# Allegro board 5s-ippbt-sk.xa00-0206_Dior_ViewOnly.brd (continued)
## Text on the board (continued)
GND: list("[Spacing] GND" "35.Shape to Route Keepout" "0 MIL [DEFAULT]" "0 MIL" "0.00 MIL" "DRC ERROR CLASS/GND" "[Shape] Route Keepout/All ((115.69 2506.43) (186.31 2577.05))" "[Gnd Shape] GND ((-373.71 -332.37) (4468.18 4481.96))" list(186.310000 2541.740000) nil)@@@list("amy_chou" "2015/01/12 09:57:41" nil "P143000034-PC" "5s-ippbt-sk.x01")@@@list("jennifer_hsu" "2015/01/12 14:36:47" nil "p143000039-pc" "5s-ippbt-sk.x01") | list("[Spacing] GND" "26.Shape to Route Keepout" "0 MIL [DEFAULT]" "0 MIL" "0.00 MIL" "DRC ERROR CLASS/GND" "[Shape] Route Keepout/All ((353.45 4291.46) (424.07 4362.08))" "[Gnd Shape] AGND ((-255.0 3453.0) (720.0 4400.0))" list(424.070000 4326.770000) nil)@@@list("amy_chou" "2015/01/12 09:57:36" nil "P143000034-PC" "5s-ippbt-sk.x01")@@@list("jennifer_hsu" "2015/01/12 14:36:44" nil "p143000039-pc" "5s-ippbt-sk.x01") | list("[Spacing] GND" "27.Shape to Route Keepout" "0 MIL [DEFAULT]" "0 MIL" "0.00 MIL" "DRC ERROR CLASS/GND" "[Shape] Route Keepout/All ((609.35 4291.46) (679.98 4362.08))" "[Gnd Shape] AGND ((-255.0 3453.0) (720.0 4400.0))" list(679.980000 4326.770000) nil)@@@list("amy_chou" "2015/01/12 09:57:37" nil "P143000034-PC" "5s-ippbt-sk.x01")@@@list("jennifer_hsu" "2015/01/12 14:36:45" nil "p143000039-pc" "5s-ippbt-sk.x01") | list("[Spacing] GND" "32.Shape to Route Keepout" "0 MIL [DEFAULT]" "0 MIL" "0.00 MIL" "DRC ERROR CLASS/GND" "[Shape] Route Keepout/All ((976.14 737.49) (1042.76 804.11))" "[Gnd Shape] GND ((-373.71 -332.37) (4468.18 4481.96))" list(1042.760000 770.800000) nil)@@@list("amy_chou" "2015/01/12 09:57:39" nil "P143000034-PC" "5s-ippbt-sk.x01")@@@list("jennifer_hsu" "2015/01/12 14:36:46" nil "p143000039-pc" "5s-ippbt-sk.x01") | list("[Spacing] GND" "28.Shape to Route Keepout" "0 MIL [DEFAULT]" "0 MIL" "0.00 MIL" "DRC ERROR CLASS/GND" "[Shape] Route Keepout/All ((1437.45 -325.97) (1524.07 -239.35))" "[Gnd Shape] GND ((-373.71 -332.37) (4468.18 4481.96))" list(1437.450000 -282.660000) nil)@@@list("amy_chou" "2015/01/12 09:57:37" nil "P143000034-PC" "5s-ippbt-sk.x01")@@@list("jennifer_hsu" "2015/01/12 14:36:45" nil "p143000039-pc" "5s-ippbt-sk.x01") | list("[Spacing] GND" "36.Shape to Route Keepout" "0 MIL [DEFAULT]" "0 MIL" "0.00 MIL" "DRC ERROR CLASS/GND" "[Shape] Route Keepout/All ((2391.48 4180.65) (2484.12 4273.28))" "[Gnd Shape] GND ((-373.71 -332.37) (4468.18 4481.96))" list(2484.120000 4226.970000) nil)@@@list("amy_chou" "2015/01/12 09:57:42" nil "P143000034-PC" "5s-ippbt-sk.x01")@@@list("jennifer_hsu" "2015/01/12 14:36:48" nil "p143000039-pc" "5s-ippbt-sk.x01") | list("[Spacing] GND" "37.Shape to Route Keepout" "0 MIL [DEFAULT]" "0 MIL" "0.00 MIL" "DRC ERROR CLASS/GND" "[Shape] Route Keepout/All ((2955.52 4114.02) (3036.14 4194.64))" "[Gnd Shape] GND ((-373.71 -332.37) (4468.18 4481.96))" list(3036.140000 4154.330000) nil)@@@list("amy_chou" "2015/01/12 09:57:42" nil "P143000034-PC" "5s-ippbt-sk.x01")@@@list("jennifer_hsu" "2015/01/12 14:36:48" nil "p143000039-pc" "5s-ippbt-sk.x01") | list("[Spacing] GND" "30.Shape to Route Keepout" "0 MIL [DEFAULT]" "0 MIL" "0.00 MIL" "DRC ERROR CLASS/GND" "[Shape] Route Keepout/All ((3031.18 -37.68) (3094.81 25.94))" "[Gnd Shape] GND ((-373.71 -332.37) (4468.18 4481.96))" list(3094.810000 -5.870000) nil)@@@list("amy_chou" "2015/01/12 09:57:38" nil "P143000034-PC" "5s-ippbt-sk.x01")@@@list("jennifer_hsu" "2015/01/12 14:36:46" nil "p143000039-pc" "5s-ippbt-sk.x01") | list("[Spacing] GND" "2.Shape to Route Keepout" "0 MIL [DEFAULT]" "0 MIL" "0.00 MIL" "DRC ERROR CLASS/GND" "[Shape] Route Keepout/All ((3082.5 3563.84) (3161.12 3642.46))" "[Gnd Shape] GND ((-373.71 -332.37) (4468.18 4481.96))" list(3121.810000 3642.460000) nil)@@@list("amy_chou" "2015/01/12 17:57:27" nil "P143000034-PC" "5s-ippbt-sk.x01")@@@list("jennifer_hsu" "2015/01/12 18:35:52" nil "p143000039-pc" "5s-ippbt-sk.x01") | list("[Spacing] GND" "29.Shape to Route Keepout" "0 MIL [DEFAULT]" "0 MIL" "0.00 MIL" "DRC ERROR CLASS/GND" "[Shape] Route Keepout/All ((3540.94 -76.81) (3604.57 -13.19))" "[Gnd Shape] GND ((-373.71 -332.37) (4468.18 4481.96))" list(3604.570000 -45.000000) nil)@@@list("amy_chou" "2015/01/12 09:57:38" nil "P143000034-PC" "5s-ippbt-sk.x01")@@@list("jennifer_hsu" "2015/01/12 14:36:45" nil "p143000039-pc" "5s-ippbt-sk.x01") | list("[Spacing] GND" "31.Shape to Route Keepout" "0 MIL [DEFAULT]" "0 MIL" "0.00 MIL" "DRC ERROR CLASS/GND" "[Shape] Route Keepout/All ((4155.45 329.33) (4242.07 415.95))" "[Gnd Shape] GND ((-373.71 -332.37) (4468.18 4481.96))" list(4242.070000 372.640000) nil)@@@list("amy_chou" "2015/01/12 09:57:39" nil "P143000034-PC" "5s-ippbt-sk.x01")@@@list("jennifer_hsu" "2015/01/12 14:36:46" nil "p143000039-pc" "5s-ippbt-sk.x01") | list("[Spacing] GND" "38.Shape to Route Keepin" "0 MIL [DEFAULT]" "0 MIL" "0.00 MIL" "DRC ERROR CLASS/GND" "[Shape] Route Keepin/All ((-373.71 -332.37) (4468.18 4481.96))" "[Gnd Shape] GND ((-373.71 -332.37) (4468.18 4481.96))" list(4299.650000 2680.720000) nil)@@@list("amy_chou" "2015/01/12 09:57:43" nil "P143000034-PC" "5s-ippbt-sk.x01")@@@list("jennifer_hsu" "2015/01/12 14:36:48" nil "p143000039-pc" "5s-ippbt-sk.x01") | list("[Spacing] GND" "33.Shape to Route Keepout" "0 MIL [DEFAULT]" "0 MIL" "0.00 MIL" "DRC ERROR CLASS/GND" "[Shape] Route Keepout/All ((4283.59 1394.18) (4509.57 1954.0))" "[Gnd Shape] GND ((-373.71 -332.37) (4468.18 4481.96))" list(4339.850000 1855.520000) nil)@@@list("amy_chou" "2015/01/12 09:57:40" nil "P143000034-PC" "5s-ippbt-sk.x01")@@@list("jennifer_hsu" "2015/01/12 14:36:47" nil "p143000039-pc" "5s-ippbt-sk.x01") | list("[Spacing] GND" "34.Shape to Route Keepout" "0 MIL [DEFAULT]" "0 MIL" "0.00 MIL" "DRC ERROR CLASS/GND" "[Shape] Route Keepout/All ((4243.45 2217.33) (4476.12 2781.09))" "[Gnd Shape] GND ((-373.71 -332.37) (4468.18 4481.96))" list(4468.180000 2780.380000) nil)@@@list("amy_chou" "2015/01/12 09:57:40" nil "P143000034-PC" "5s-ippbt-sk.x01")@@@list("jennifer_hsu" "2015/01/12 14:36:47" nil "p143000039-pc" "5s-ippbt-sk.x01")
User.28: R | 1 | 12 | 24 | 36 | E317539 | F2 | H14 | AU1 | CR6 | Y12 | SW10 | P13 | XBT1 | 2-4 | Clear CMOS | 1-3 | Clear PW | 3-4 | Default | P110 | E69 | P12 | TEL:(02)81439001 FAX:(02)28973868 | TAIPEI | www.pegatroncorp.com | DESIGNED BY PEGATRON CORPORATION | H1 | H3 | PCB MADE IN CHINA | REV:X01 | H4 | H2 | DESIGNER: | DATE: | LAY#: | 2015.01.12/18:38:52 | 5S-IPPBT-SK.X01 | AMY_CHOU | J56 | J27 | J8 | SFIS | J17 | J137 | J125 | E4 | ALL RIGHTS RESERVED | www.dell.com | COPYRIGHT 2015,01 | PJ1 | J218 | J11 | J133 | J219 | R&D DEPARTMENT/ENGINEER: | PROJECT DESCRIPTION: | MODEL NAME: | IPPBT-SK | BU5/Robert_Teng | Main Board | REV. | X01 | SILKSCREEN | PRIMARY-SIDE | N14939 | D33D66
User.29: 1 | 7 | 6 | 11 | 16 | 19 | 204 | 203 | 8 | 24 | 64 | 32 | 96 | 2 | 13 | H7 | H23 | H22 | XU1 | J134 | 14 | H20 | H21 | H8 | P70 | PU8 | PU3 | Y10 | LU1 | UU3 | Y24 | Y5 | U24 | PU9 | 21 | U23 | TEL:(02)81439001 FAX:(02)28973868 | TAIPEI | www.pegatroncorp.com | DESIGNED BY PEGATRON CORPORATION | DESIGNER: | DATE: | LAY#: | 2015.01.12/18:38:52 | 5S-IPPBT-SK.X01 | AMY_CHOU | XMM1 | R&D DEPARTMENT/ENGINEER: | PROJECT DESCRIPTION: | MODEL NAME: | IPPBT-SK | BU5/Robert_Teng | Main Board | REV. | X01 | SILKSCREEN | SECONDARY-SIDE
User.36: FIGURE | SIZE | 10.0 | 12.0 | 18.0 | 23.0 | 24.0 | 28.0 | 29.0 | 34.0 | 36.0 | 38.0 | 46.0 | 63.0 | 146.0 | 165.0 | 40.0 | 43.0 | 47.0 | 55.0 | 57.0 | 59.0 | 65.0 | 67.0 | 69.0 | 89.0 | 118.0 | 157.0 | 29.0x18.0 | 33.0x14.0 | 36.0x16.0 | 44.0x18.0 | 46.0x20.0 | 47.0x31.0 | 51.0x31.0 | 67.0x31.0 | 68.0x26.0 | 79.0x24.0 | 87.0x31.0 | 88.0x26.0 | 101.0x24.0 | 114.0x39.0 | 131.0x18.0 | DRILL CHART: TOP to BOTTOM (1 to 6) | ALL UNITS ARE IN MILS | TOLERANCE | +3.0/-3.0 | +2.0/-2.0 | PLATED | NON-PLATED | ROTATION | - | 0.000 | 90.000 | QTY | 2306 | 73 | 266 | 19 | 20 | 9 | 6 | 10 | 8 | 4 | 3 | 2 | 1 | 5 | 2807 | TOTAL HOLES:
